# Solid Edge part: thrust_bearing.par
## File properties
Title: Thrust bearing
Author: Abhinav Rai
Template: Normal.par
Last saved by: TIET
Revision: 13
Application: Solid Edge
Accuracy: 0.99
Material: aluminum
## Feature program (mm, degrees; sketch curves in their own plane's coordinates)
sketch for "unnamed RevolvedProtrusion 1" plane through (0, 0, 0) normal (0, -1, 0) x-axis (1, 0, 0)
  line (47.625, 16.8036) -> (66.929, 16.8036)
  line (66.929, 16.8036) -> (73.025, 10.7076)
  line (73.025, 10.7076) -> (73.025, -12.0254)
  line (73.025, -12.0254) -> (66.929, -18.1214)
  line (66.929, -18.1214) -> (47.625, -18.1214)
  line (47.625, -18.1214) -> (47.625, -7.0089)
  line (61.5714, -7.0089) -> (47.625, -7.0089)
  line (61.5714, 5.6911) -> (61.5714, -7.0089)
  line (47.625, 5.6911) -> (61.5714, 5.6911)
  line (47.625, 5.6911) -> (47.625, 16.8036)
revolve "unnamed RevolvedProtrusion 1" add full turn 360 deg
sketch for "unnamed RevolvedProtrusion 2" plane through (0, 0, 0) normal (1, 0, 0) x-axis (0, 1, 0)
  line (69.977, 13.7556) -> (73.0652, 13.7556)
  line (73.0652, 13.7556) -> (74.6125, 12.2083)
  line (74.6125, 12.2083) -> (74.6125, -13.4669)
  line (74.6125, -13.4669) -> (73.006, -15.0734)
  line (73.006, -15.0734) -> (69.977, -15.0734)
revolve "unnamed RevolvedProtrusion 2" add full turn 360 deg
sketch for "unnamed RevolvedProtrusion 3" plane through (0, 0, 0) normal (0, -1, 0) x-axis (1, 0, 0)
revolve "unnamed RevolvedProtrusion 3" add full turn 360 deg about sketch line (-54.9674, 10.1232) -> (-54.9674, -18.1214)
pattern "unnamed Pattern 1" of "unnamed RevolvedProtrusion 3"
pattern "unnamed Pattern 2"
sketch for "unnamed RevolvedProtrusion 4" plane through (-58.658, 0, 54.4016) normal (0, -1, 0) x-axis (1, 0, 0)
revolve "unnamed RevolvedProtrusion 4" add full turn 360 deg
sketch for "unnamed RevolvedProtrusion 5" plane through (0, -119.6728, -47.0787) normal (1, 0, 0) x-axis (0, 1, 0)
revolve "unnamed RevolvedProtrusion 5" add full turn 360 deg
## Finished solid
Body 1: solid body, 39 faces, 39 edges, 25 vertices.
  Faces by surface: torus 25, plane 6, cone 4, cylinder 4
  Edges by curve: circle 39
Bounding box of the edges (mm; curved faces can reach further): 149.225 x 149.225 x 34.925, from (-74.6125, -74.6125, -18.1214) to (74.6125, 74.6125, 16.8036).
Cylindrical faces by radius (mm): R47.625 x2, R61.5714 x1, R74.6125 x1
Conical faces (half-angle, radius in mm at the cone's reference point): 45 deg R66.929 x1, 45 deg R73.025 x1, 45 deg R73.0652 x1, 45 deg R74.6125 x1
Toroidal faces (ring radius, tube radius in mm): R-1.578 r6.604 x25
Planar faces by outward normal: +z 3, -z 3
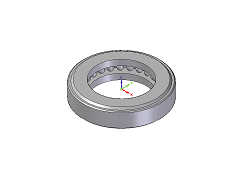
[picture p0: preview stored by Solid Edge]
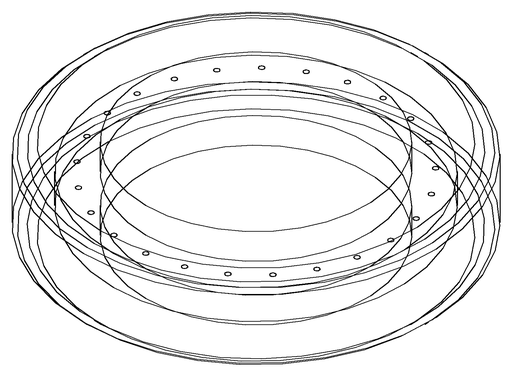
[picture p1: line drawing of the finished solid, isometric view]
